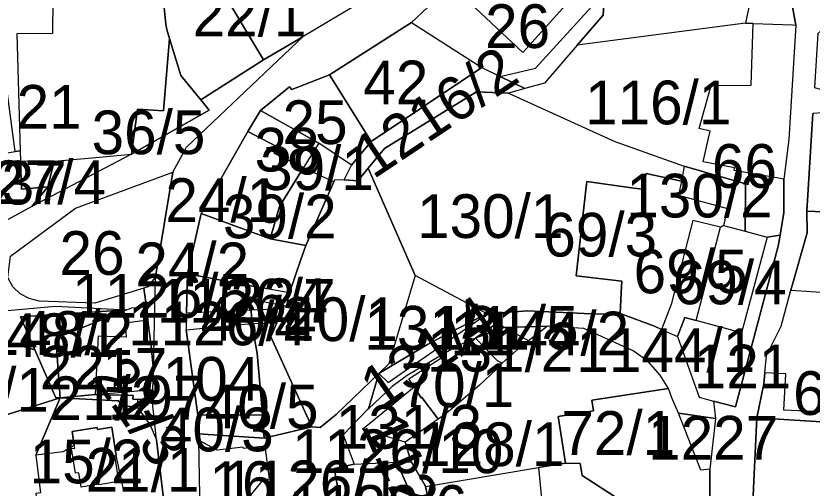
# Model space of a CAD drawing. Extents: x -623250 to -619626, y -1079612 to -1075424.
# Drawn here: x -621601 to -621418.9, y -1077445.8 to -1077337.8 of the extents above; entities that cross this region are included whole.
import ezdxf

# ---------------------------------------------------------------- set-up
doc = ezdxf.new("R2010")
doc.units = 0
doc.layers.add('Parcela nároku', color=7, linetype='Continuous')
doc.layers.add('Parcelní číslo', color=7, linetype='Continuous')

msp = doc.modelspace()

# ---------------------------------------------------------------- linework, layer by layer
at = {"layer": 'Parcela nároku'}
for points in [[(-621600.79, -1077341.91), (-621599.98, -1077368.66), (-621601.14, -1077368.85), (-621608.91, -1077310.81), (-621614.46, -1077275.5), (-621617.74, -1077254.62), (-621618.44, -1077250.2), (-621584.31, -1077246.2), (-621576.81, -1077248.47), (-621571.17, -1077298.59), (-621567.58, -1077330.5), (-621592.44, -1077330.4), (-621592.59, -1077340.5), (-621592.59, -1077341.84)], [(-621538.85, -1077280.06), (-621571.17, -1077298.59), (-621567.58, -1077330.5), (-621566.7, -1077339.72), (-621566.45, -1077340.93), (-621565.82, -1077343), (-621563.28, -1077351.43), (-621558.7, -1077357.03), (-621544.35, -1077347.86), (-621555.55, -1077329.09), (-621547.19, -1077324.12), (-621539.75, -1077319.7), (-621541.19, -1077317.29), (-621534.31, -1077313.2), (-621540.47, -1077302.78), (-621526.88, -1077291.7), (-621533.5, -1077284.61)], [(-621434.34, -1077279.24), (-621430.86, -1077291.13), (-621432.17, -1077292.28), (-621438.74, -1077291.36), (-621448.7, -1077303.36), (-621460.94, -1077315.92), (-621466.21, -1077330.18), (-621466.69, -1077337.64), (-621472.59, -1077344.5), (-621480.06, -1077353.2), (-621484.6, -1077354.45), (-621490.21, -1077351.69), (-621482.13, -1077349.74), (-621469.37, -1077335.72), (-621469.69, -1077327.4), (-621464.19, -1077314.37), (-621453.57, -1077303.62), (-621441.05, -1077289.32), (-621435.63, -1077281.18)], [(-621440.32, -1077334.33), (-621433.33, -1077335.82), (-621434.1, -1077339.5), (-621472.59, -1077344.5), (-621466.69, -1077337.64), (-621466.21, -1077330.18), (-621460.94, -1077315.92), (-621448.7, -1077303.36), (-621438.74, -1077291.36), (-621432.17, -1077292.28), (-621427.72, -1077298.01), (-621426.4, -1077312.7), (-621428.83, -1077304.68), (-621438.65, -1077307.63), (-621436.09, -1077315.53), (-621436.48, -1077317.28)], [(-621426.4, -1077312.7), (-621428.83, -1077304.68), (-621438.65, -1077307.63), (-621436.09, -1077315.53), (-621436.48, -1077317.28), (-621440.32, -1077334.33), (-621433.33, -1077335.82), (-621434.1, -1077339.5), (-621432.38, -1077339.59), (-621423.38, -1077339.89), (-621422.64, -1077339.94), (-621424.02, -1077331.91), (-621426.21, -1077319.12)], [(-621534.31, -1077313.2), (-621541.19, -1077317.29), (-621539.75, -1077319.7), (-621547.19, -1077324.12), (-621555.55, -1077329.09), (-621544.35, -1077347.86), (-621536.28, -1077343.1), (-621535.09, -1077342.4), (-621521.75, -1077334.48), (-621530.34, -1077319.92)], [(-621492.61, -1077328.02), (-621495.56, -1077325.19), (-621510.49, -1077339.36), (-621494.39, -1077349.63), (-621490.21, -1077351.69), (-621482.13, -1077349.74), (-621469.37, -1077335.72), (-621469.69, -1077327.4), (-621482.14, -1077312.1), (-621489.64, -1077319.57), (-621479, -1077329.07), (-621473.85, -1077333.67), (-621485.07, -1077346.16), (-621498.3, -1077333.67)], [(-621473.85, -1077333.67), (-621479, -1077329.07), (-621489.64, -1077319.57), (-621495.56, -1077325.19), (-621492.61, -1077328.02), (-621498.3, -1077333.67), (-621485.07, -1077346.16)], [(-621592.59, -1077340.5), (-621592.59, -1077341.84), (-621600.79, -1077341.91), (-621599.98, -1077368.66), (-621599.89, -1077370.95), (-621592.24, -1077371.02), (-621590.5, -1077370.88), (-621582.71, -1077370.17), (-621574.55, -1077369.43), (-621573.15, -1077359.17), (-621567.25, -1077359.56), (-621565.82, -1077343), (-621566.45, -1077340.93), (-621566.7, -1077339.72), (-621567.58, -1077330.5), (-621592.44, -1077330.4)], [(-621379.17, -1077372.99), (-621383.87, -1077336.3), (-621412.76, -1077337.56), (-621417.57, -1077341.86), (-621418.32, -1077354.2), (-621414.45, -1077355.34), (-621414.57, -1077350.94), (-621414.74, -1077344.54), (-621399.69, -1077344.22), (-621399.53, -1077350.53), (-621399.5, -1077351.73), (-621390.49, -1077351.5), (-621390.14, -1077367.74), (-621399.09, -1077368.05), (-621411.39, -1077368.36), (-621414.09, -1077368.43), (-621414.24, -1077362.93), (-621414.33, -1077359.83), (-621418.69, -1077360.17), (-621420.08, -1077382.44), (-621380.43, -1077384.11)], [(-621510.49, -1077339.36), (-621494.39, -1077349.63), (-621519.69, -1077366.53), (-621529.22, -1077351.28)], [(-621434.13, -1077376.21), (-621434.19, -1077387.03), (-621429.2, -1077388.44), (-621426.22, -1077387.99), (-621425.34, -1077382.75), (-621425.37, -1077375.13), (-621426.96, -1077374.88), (-621436.7, -1077373.18), (-621436.67, -1077372.57), (-621443.81, -1077371.16), (-621442.58, -1077365.76), (-621442.21, -1077364.21), (-621444.71, -1077363.56), (-621442.16, -1077354.24), (-621442.03, -1077353.76), (-621432.85, -1077353.64), (-621432.38, -1077339.59), (-621434.1, -1077339.5), (-621472.59, -1077344.5), (-621480.06, -1077353.2), (-621484.6, -1077354.45), (-621488.31, -1077355.48), (-621464.03, -1077366.57), (-621448.14, -1077372.19)], [(-621436.7, -1077373.18), (-621436.67, -1077372.57), (-621443.81, -1077371.16), (-621442.58, -1077365.76), (-621442.21, -1077364.21), (-621444.71, -1077363.56), (-621442.16, -1077354.24), (-621442.03, -1077353.76), (-621432.85, -1077353.64), (-621432.38, -1077339.59), (-621423.38, -1077339.89), (-621422.64, -1077339.94), (-621424.22, -1077366.08), (-621425.37, -1077375.13), (-621426.96, -1077374.88)], [(-621558.7, -1077357.03), (-621563.28, -1077351.43), (-621565.82, -1077343), (-621567.25, -1077359.56), (-621573.15, -1077359.17), (-621574.55, -1077369.43), (-621556.8, -1077359.35)], [(-621524.2, -1077371.94), (-621519.69, -1077366.53), (-621494.39, -1077349.63), (-621490.21, -1077351.69), (-621484.6, -1077354.45), (-621488.31, -1077355.48), (-621495.61, -1077355.2), (-621516.65, -1077368.16), (-621520.4, -1077372.67), (-621522.76, -1077375.51), (-621525.93, -1077375.32)], [(-621545.03, -1077359.49), (-621538.38, -1077354.07), (-621537.9, -1077354.66), (-621529.22, -1077351.28), (-621519.69, -1077366.53), (-621524.2, -1077371.94), (-621531.73, -1077366.96)], [(-621472.87, -1077397.29), (-621462.39, -1077398.51), (-621462.44, -1077399.6), (-621462.78, -1077405.91), (-621467.82, -1077406.05), (-621483.88, -1077405.25), (-621493.23, -1077405.99), (-621509.64, -1077397.21), (-621520.4, -1077372.67), (-621516.65, -1077368.16), (-621495.61, -1077355.2), (-621488.31, -1077355.48), (-621464.03, -1077366.57), (-621448.14, -1077372.19), (-621448.79, -1077375.65), (-621456.84, -1077373.89), (-621457.65, -1077377.44), (-621459.62, -1077377.18), (-621470.4, -1077375.71), (-621470.64, -1077377.59)], [(-621545.03, -1077359.49), (-621531.73, -1077366.96), (-621535.2, -1077372.52), (-621541.94, -1077369.2), (-621541.22, -1077367.79), (-621547.92, -1077364.23)], [(-621558.62, -1077383), (-621547.92, -1077364.23), (-621541.22, -1077367.79), (-621541.94, -1077369.2), (-621535.2, -1077372.52), (-621540.69, -1077381.38), (-621542.85, -1077388.78), (-621551.12, -1077385.75)], [(-621531.73, -1077366.96), (-621535.2, -1077372.52), (-621528.3, -1077375.8), (-621528.05, -1077375.2), (-621525.93, -1077375.32), (-621524.2, -1077371.94)], [(-621601.14, -1077368.85), (-621599.98, -1077368.66), (-621599.89, -1077370.95), (-621599.68, -1077377.48), (-621593.69, -1077376.92), (-621597.29, -1077381.44), (-621627.71, -1077398.04), (-621629.08, -1077393.14), (-621618.11, -1077380.62), (-621616.18, -1077371.29), (-621610.38, -1077370.32)], [(-621592.24, -1077371.02), (-621590.5, -1077370.88), (-621582.71, -1077370.17), (-621574.55, -1077369.43), (-621597.29, -1077381.44), (-621593.69, -1077376.92)], [(-621599.89, -1077370.95), (-621592.24, -1077371.02), (-621593.69, -1077376.92), (-621599.68, -1077377.48)], [(-621587.33, -1077381.8), (-621565.08, -1077373.54), (-621569.08, -1077397.48), (-621570.82, -1077399.79), (-621571.73, -1077400.07), (-621582.93, -1077403.5), (-621595.64, -1077403.04), (-621597.93, -1077402.44), (-621599.99, -1077401.39), (-621601.64, -1077399.77), (-621602.8, -1077397.67), (-621602.22, -1077392.75)], [(-621535.2, -1077372.52), (-621528.3, -1077375.8), (-621534.63, -1077390.3), (-621542.85, -1077388.78), (-621540.69, -1077381.38)], [(-621528.3, -1077375.8), (-621528.05, -1077375.2), (-621525.93, -1077375.32), (-621522.76, -1077375.51), (-621520.4, -1077372.67), (-621509.64, -1077397.21), (-621515.68, -1077417.42), (-621517.95, -1077419.57), (-621527.71, -1077428.99), (-621531.37, -1077431.97), (-621533.26, -1077431.82), (-621542.67, -1077411.2), (-621541.3, -1077408), (-621539.94, -1077404.78), (-621539.64, -1077404.07), (-621538.98, -1077404.2), (-621538.42, -1077401.19), (-621535.82, -1077393.52), (-621534.63, -1077390.3)], [(-621448.79, -1077375.65), (-621449.45, -1077378.83), (-621438.25, -1077381.86), (-621439.12, -1077385.73), (-621434.19, -1077387.03), (-621434.13, -1077376.21), (-621448.14, -1077372.19)], [(-621470.4, -1077375.71), (-621459.62, -1077377.18), (-621457.65, -1077377.44), (-621456.84, -1077373.89), (-621448.79, -1077375.65), (-621449.45, -1077378.83), (-621438.25, -1077381.86), (-621439.12, -1077385.73), (-621439.86, -1077386.13), (-621446.17, -1077384.61), (-621451.13, -1077403.82), (-621453.32, -1077409.51), (-621454.95, -1077408.78), (-621462.78, -1077405.91), (-621462.44, -1077399.6), (-621462.39, -1077398.51), (-621472.87, -1077397.29), (-621470.64, -1077377.59)], [(-621420.01, -1077387.44), (-621423.72, -1077400.54), (-621405.16, -1077401.74), (-621405.62, -1077410.25), (-621406.08, -1077418.95), (-621406.7, -1077428.87), (-621425.38, -1077428), (-621424.88, -1077419.72), (-621429.71, -1077419.47), (-621429.96, -1077421.94), (-621431.55, -1077429.78), (-621387.12, -1077432.52), (-621384.11, -1077410.75), (-621380.43, -1077384.11), (-621420.08, -1077382.44)], [(-621542.85, -1077388.78), (-621534.63, -1077390.3), (-621535.82, -1077393.52), (-621538.42, -1077401.19), (-621544.35, -1077400.08), (-621561.72, -1077396.82), (-621558.62, -1077383), (-621551.12, -1077385.75)], [(-621446.17, -1077384.61), (-621451.13, -1077403.82), (-621453.32, -1077409.51), (-621449.67, -1077411.15), (-621448.01, -1077406.8), (-621445.38, -1077407.51), (-621439.86, -1077386.13)], [(-621445.38, -1077407.51), (-621439.86, -1077386.13), (-621439.12, -1077385.73), (-621434.19, -1077387.03), (-621429.2, -1077388.44), (-621435, -1077410.33)], [(-621445.38, -1077407.51), (-621448.01, -1077406.8), (-621449.67, -1077411.15), (-621444.7, -1077425.04), (-621441.44, -1077425.9), (-621436.38, -1077427.24), (-621426.64, -1077390.48), (-621426.22, -1077387.99), (-621429.2, -1077388.44), (-621435, -1077410.33)], [(-621544.9, -1077403.08), (-621539.64, -1077404.07), (-621539.94, -1077404.78), (-621547.14, -1077405.1), (-621561.94, -1077405.77), (-621561.72, -1077396.82), (-621544.35, -1077400.08)], [(-621515.68, -1077417.42), (-621517.95, -1077419.57), (-621515.65, -1077418.24), (-621511.33, -1077415.66), (-621506.84, -1077412.99), (-621501.61, -1077410.13), (-621495.26, -1077406.93), (-621493.23, -1077405.99), (-621509.64, -1077397.21)], [(-621570.82, -1077399.79), (-621571.73, -1077400.07), (-621571.13, -1077404.37), (-621571.05, -1077404.91), (-621570.78, -1077407.39), (-621569.98, -1077414.08), (-621569.54, -1077418.79), (-621569.08, -1077397.48)], [(-621538.42, -1077401.19), (-621544.35, -1077400.08), (-621544.9, -1077403.08), (-621539.64, -1077404.07), (-621538.98, -1077404.2)], [(-621425.97, -1077408.77), (-621423.72, -1077400.54), (-621405.16, -1077401.74), (-621405.62, -1077410.25), (-621406.08, -1077418.95), (-621406.7, -1077428.87), (-621425.38, -1077428), (-621424.88, -1077419.72), (-621429.71, -1077419.47), (-621429.3, -1077415.48)], [(-621607.45, -1077411.04), (-621603.75, -1077405.28), (-621591.99, -1077404.24), (-621575.61, -1077405.07), (-621599.94, -1077406.64), (-621596.63, -1077414.23)], [(-621574.48, -1077404.61), (-621571.13, -1077404.37), (-621571.05, -1077404.91), (-621570.78, -1077407.39), (-621575.95, -1077408.09), (-621575.72, -1077411.26), (-621582.16, -1077411.03), (-621582.82, -1077424.39), (-621590.81, -1077425.21), (-621591.83, -1077411.56), (-621575.61, -1077405.07)], [(-621591.83, -1077411.56), (-621590.81, -1077425.21), (-621591.86, -1077425.16), (-621596.63, -1077414.23), (-621599.94, -1077406.64), (-621575.61, -1077405.07)], [(-621547.14, -1077405.1), (-621561.94, -1077405.77), (-621562.03, -1077409.62), (-621547.03, -1077408.14)], [(-621539.94, -1077404.78), (-621547.14, -1077405.1), (-621547.03, -1077408.14), (-621541.3, -1077408)], [(-621517.95, -1077419.57), (-621515.81, -1077421.63), (-621493.23, -1077405.99), (-621483.88, -1077405.25), (-621467.82, -1077406.05), (-621462.78, -1077405.91), (-621454.95, -1077408.78), (-621453.32, -1077409.51), (-621449.67, -1077411.15), (-621444.7, -1077425.04), (-621441.44, -1077425.9), (-621441.01, -1077429.91), (-621449.46, -1077428.7), (-621450.93, -1077425.2), (-621451.75, -1077423), (-621453.66, -1077420.01), (-621456.4, -1077416.9), (-621459.78, -1077414.4), (-621471.08, -1077409.3), (-621479.38, -1077408.78), (-621487, -1077409.02), (-621489.26, -1077409.05), (-621490.98, -1077408.1), (-621495.85, -1077411.52), (-621499.95, -1077413.28), (-621505.31, -1077416.39), (-621511.49, -1077420.06), (-621514.92, -1077422.55), (-621520.35, -1077427.68)], [(-621511.33, -1077415.66), (-621515.65, -1077418.24), (-621517.95, -1077419.57), (-621515.81, -1077421.63), (-621493.23, -1077405.99), (-621495.26, -1077406.93), (-621501.61, -1077410.13), (-621506.84, -1077412.99)], [(-621582.16, -1077411.03), (-621582.82, -1077424.39), (-621569.69, -1077423.27), (-621569.54, -1077418.79), (-621569.98, -1077414.08), (-621570.78, -1077407.39), (-621575.95, -1077408.09), (-621575.72, -1077411.26)], [(-621547.03, -1077408.14), (-621545.76, -1077415), (-621545.1, -1077422.71), (-621544.56, -1077429.09), (-621559.34, -1077429.16), (-621562.03, -1077409.62)], [(-621542.67, -1077411.2), (-621533.26, -1077431.82), (-621544.21, -1077434.42), (-621544.56, -1077429.09), (-621545.1, -1077422.71), (-621545.76, -1077415), (-621547.03, -1077408.14), (-621541.3, -1077408)], [(-621495.85, -1077411.52), (-621490.98, -1077408.1), (-621489.26, -1077409.05)], [(-621502.93, -1077429.08), (-621504.38, -1077430.07), (-621511.92, -1077435.34), (-621510.57, -1077439.83), (-621507.3, -1077445.44), (-621481.49, -1077441.1), (-621475.26, -1077440.11), (-621476.98, -1077429.42), (-621468.9, -1077428.12), (-621469.29, -1077425.7), (-621466.76, -1077425.29), (-621451.75, -1077423), (-621453.66, -1077420.01), (-621456.4, -1077416.9), (-621459.78, -1077414.4), (-621471.08, -1077409.3), (-621479.38, -1077408.78), (-621483.72, -1077412.1), (-621484.93, -1077413), (-621489.79, -1077417.27), (-621491.17, -1077418.72), (-621494.92, -1077422.28), (-621500.25, -1077426.86)], [(-621489.26, -1077409.05), (-621495.85, -1077411.52), (-621490.9, -1077416.64), (-621489.79, -1077417.27), (-621484.93, -1077413), (-621483.72, -1077412.1)], [(-621487, -1077409.02), (-621479.38, -1077408.78), (-621483.72, -1077412.1), (-621489.26, -1077409.05)], [(-621623.02, -1077425.7), (-621607.45, -1077411.04), (-621596.63, -1077414.23), (-621591.86, -1077425.16), (-621590.81, -1077425.21), (-621608.27, -1077430.64), (-621625.29, -1077427.92)], [(-621514.92, -1077422.55), (-621520.35, -1077427.68), (-621520.64, -1077427.95), (-621526.14, -1077433.6), (-621523.62, -1077440.31), (-621513.83, -1077439.85), (-621510.57, -1077439.83), (-621511.92, -1077435.34), (-621521.73, -1077432.32), (-621509.91, -1077422.66), (-621511.09, -1077420.83), (-621503.6, -1077415.98), (-621502.71, -1077417.23), (-621501.46, -1077416.29), (-621499.1, -1077414.64), (-621495.85, -1077411.52), (-621499.95, -1077413.28), (-621505.31, -1077416.39), (-621511.49, -1077420.06)], [(-621495.85, -1077411.52), (-621490.9, -1077416.64), (-621489.79, -1077417.27), (-621491.17, -1077418.72), (-621494.92, -1077422.28), (-621500.25, -1077426.86), (-621502.93, -1077429.08), (-621504.38, -1077430.07), (-621504.79, -1077429.52), (-621508.12, -1077425.06), (-621508.28, -1077425.17), (-621509.91, -1077422.66), (-621511.09, -1077420.83), (-621503.6, -1077415.98), (-621502.71, -1077417.23), (-621501.46, -1077416.29), (-621499.1, -1077414.64)], [(-621508.12, -1077425.06), (-621504.79, -1077429.52), (-621504.38, -1077430.07), (-621511.92, -1077435.34), (-621521.73, -1077432.32), (-621509.91, -1077422.66), (-621508.28, -1077425.17)], [(-621574.2, -1077425.49), (-621573.14, -1077425.56), (-621573.22, -1077427.34), (-621576.22, -1077427), (-621577.59, -1077425.88), (-621590.81, -1077425.21), (-621582.82, -1077424.39), (-621574.17, -1077424.62)], [(-621582.82, -1077424.39), (-621569.69, -1077423.27), (-621569.77, -1077425.55), (-621573.14, -1077425.56), (-621574.2, -1077425.49), (-621574.17, -1077424.62)], [(-621451.75, -1077423), (-621466.76, -1077425.29), (-621469.29, -1077425.7), (-621468.9, -1077428.12), (-621476.98, -1077429.42), (-621475.26, -1077440.11), (-621471.93, -1077440.18), (-621471.5, -1077442.95), (-621452.51, -1077455.2), (-621442.23, -1077454.31), (-621442.3, -1077441.52), (-621444.35, -1077441.74), (-621449.46, -1077428.7), (-621450.93, -1077425.2)], [(-621651.71, -1077428.55), (-621625.29, -1077427.92), (-621608.27, -1077430.64), (-621590.81, -1077425.21), (-621596.41, -1077438.29), (-621595.37, -1077446.92), (-621596.41, -1077447.05), (-621596.32, -1077447.8), (-621599.98, -1077451.17), (-621607.92, -1077449.11), (-621609.14, -1077444.92), (-621615.21, -1077439.45), (-621626.72, -1077438.85), (-621649.84, -1077437.65)], [(-621568.85, -1077434.75), (-621569.77, -1077425.55), (-621573.14, -1077425.56), (-621573.22, -1077427.34), (-621570.36, -1077431.24)], [(-621544.56, -1077429.09), (-621544.21, -1077434.42), (-621559.26, -1077433.41), (-621559.34, -1077429.16)], [(-621449.46, -1077428.7), (-621441.01, -1077429.91), (-621442.3, -1077441.52), (-621444.35, -1077441.74)], [(-621431.19, -1077464.42), (-621432.42, -1077476.42), (-621394.2, -1077479.27), (-621389.22, -1077446.41), (-621387.12, -1077432.52), (-621431.55, -1077429.78), (-621432.54, -1077450.72)], [(-621588.25, -1077436.78), (-621587.51, -1077436.66), (-621587.61, -1077436.07), (-621588.12, -1077432.87), (-621582.36, -1077431.97), (-621582.29, -1077432.4), (-621579.02, -1077431.89), (-621578.01, -1077438.34), (-621578.41, -1077438.46), (-621577.65, -1077443.25), (-621577.51, -1077444.3), (-621582.01, -1077445.04), (-621582.03, -1077444.94), (-621586.06, -1077445.6), (-621586.61, -1077442.29), (-621587.31, -1077442.4)], [(-621547.56, -1077449.24), (-621547.71, -1077447.97), (-621544.37, -1077443.86), (-621543.01, -1077443.69), (-621543.93, -1077436.2), (-621548.94, -1077436.76), (-621548.97, -1077436.47), (-621554.97, -1077437.15), (-621559.23, -1077434.88), (-621558.89, -1077451.75), (-621556.54, -1077458.83), (-621548.86, -1077449.39)], [(-621523.62, -1077440.31), (-621513.83, -1077439.85), (-621507.7, -1077453.97), (-621510.81, -1077454.77), (-621512.86, -1077470.31), (-621518.98, -1077469.95), (-621519.69, -1077452.67), (-621524.33, -1077452.43), (-621526.15, -1077452.32), (-621528.22, -1077441.35)], [(-621507.3, -1077445.44), (-621505.58, -1077453.42), (-621507.7, -1077453.97), (-621513.83, -1077439.85), (-621510.57, -1077439.83)], [(-621507.3, -1077445.44), (-621481.49, -1077441.1), (-621479.17, -1077464.9), (-621503.43, -1077463.41), (-621505.07, -1077455.79), (-621505.58, -1077453.42)], [(-621442.07, -1077471), (-621442.35, -1077467.18), (-621441.68, -1077467.22), (-621442.23, -1077454.31), (-621452.51, -1077455.2), (-621471.5, -1077442.95), (-621471.93, -1077440.18), (-621475.26, -1077440.11), (-621481.49, -1077441.1), (-621479.17, -1077464.9), (-621467.73, -1077465.6), (-621454.56, -1077468.37)]]:
    msp.add_lwpolyline(points, close=True, dxfattribs=at)
for points in [[(-621495.56, -1077325.19), (-621510.49, -1077339.36), (-621529.22, -1077351.28), (-621537.9, -1077354.66), (-621538.38, -1077354.07), (-621545.03, -1077359.49), (-621547.92, -1077364.23), (-621558.62, -1077383), (-621561.72, -1077396.82), (-621561.94, -1077405.77), (-621562.03, -1077409.62), (-621559.34, -1077429.16), (-621559.26, -1077433.41), (-621559.23, -1077434.88), (-621558.89, -1077451.75)], [(-621424.02, -1077331.91), (-621422.64, -1077339.94), (-621424.22, -1077366.08), (-621425.37, -1077375.13), (-621425.34, -1077382.75), (-621426.22, -1077387.99), (-621426.64, -1077390.48), (-621436.38, -1077427.24), (-621441.44, -1077425.9), (-621441.01, -1077429.91), (-621442.3, -1077441.52), (-621442.23, -1077454.31)], [(-621566.72, -1077452.69), (-621568.85, -1077434.75), (-621569.77, -1077425.55), (-621569.69, -1077423.27), (-621569.54, -1077418.79), (-621569.08, -1077397.48), (-621565.08, -1077373.54), (-621561.99, -1077367.81), (-621535.09, -1077342.4), (-621521.75, -1077334.48)], [(-621602.22, -1077392.75), (-621587.33, -1077381.8), (-621565.08, -1077373.54), (-621561.99, -1077367.81), (-621535.09, -1077342.4), (-621536.28, -1077343.1), (-621544.35, -1077347.86), (-621558.7, -1077357.03), (-621556.8, -1077359.35), (-621574.55, -1077369.43), (-621597.29, -1077381.44), (-621627.71, -1077398.04)], [(-621432.54, -1077450.72), (-621431.55, -1077429.78), (-621429.96, -1077421.94), (-621429.71, -1077419.47), (-621429.3, -1077415.48), (-621425.97, -1077408.77), (-621423.72, -1077400.54), (-621420.01, -1077387.44), (-621420.08, -1077382.44), (-621418.69, -1077360.17)], [(-621603.75, -1077405.28), (-621591.99, -1077404.24), (-621575.61, -1077405.07), (-621574.48, -1077404.61), (-621571.13, -1077404.37), (-621571.73, -1077400.07), (-621582.93, -1077403.5), (-621595.64, -1077403.04), (-621597.93, -1077402.44), (-621599.99, -1077401.39), (-621601.64, -1077399.77)], [(-621547.71, -1077447.97), (-621544.37, -1077443.86), (-621543.01, -1077443.69), (-621543.93, -1077436.2), (-621548.94, -1077436.76), (-621548.97, -1077436.47), (-621554.97, -1077437.15), (-621559.23, -1077434.88), (-621559.26, -1077433.41), (-621544.21, -1077434.42), (-621533.26, -1077431.82), (-621531.37, -1077431.97), (-621527.71, -1077428.99), (-621517.95, -1077419.57), (-621520.35, -1077427.68), (-621520.64, -1077427.95), (-621526.14, -1077433.6), (-621523.62, -1077440.31), (-621528.22, -1077441.35), (-621526.15, -1077452.32)], [(-621576.31, -1077446.48), (-621578.01, -1077438.34), (-621579.02, -1077431.89), (-621582.29, -1077432.4), (-621582.36, -1077431.97), (-621588.12, -1077432.87), (-621587.61, -1077436.07), (-621590.26, -1077437.55), (-621596.41, -1077438.29), (-621590.81, -1077425.21), (-621577.59, -1077425.88), (-621576.22, -1077427), (-621573.22, -1077427.34), (-621570.36, -1077431.24), (-621568.85, -1077434.75), (-621566.72, -1077452.69)], [(-621576.31, -1077446.48), (-621578.01, -1077438.34), (-621578.41, -1077438.46), (-621577.65, -1077443.25), (-621577.51, -1077444.3), (-621582.01, -1077445.04), (-621582.03, -1077444.94), (-621586.06, -1077445.6), (-621586.61, -1077442.29), (-621587.31, -1077442.4), (-621588.25, -1077436.78), (-621587.51, -1077436.66), (-621587.61, -1077436.07), (-621590.26, -1077437.55), (-621596.41, -1077438.29), (-621595.37, -1077446.92)]]:
    msp.add_lwpolyline(points, dxfattribs=at)

# ---------------------------------------------------------------- texts
at = {"layer": 'Parcelní číslo'}
for s, p in [('22/1', (-621560.55, -1077342.51)), ('26', (-621493.67, -1077345.16)), ('42', (-621521.53, -1077358.04)), ('21', (-621600.8, -1077363.62)), ('116/1', (-621470.81, -1077362.62)), ('25', (-621539.99, -1077367.13)), ('36/5', (-621583.66, -1077369.45)), ('38', (-621546.4, -1077373.41)), ('39/1', (-621545.13, -1077377.65)), ('66', (-621441.81, -1077377.14)), ('27/4', (-621606.37, -1077380.87)), ('37', (-621604.22, -1077380.95)), ('130/2', (-621461.37, -1077383.92)), ('24/1', (-621566.78, -1077384.95)), ('39/2', (-621553.63, -1077388.68)), ('130/1', (-621509.23, -1077388.61)), ('69/3', (-621480.36, -1077392.85)), ('26', (-621590.99, -1077397.04)), ('24/2', (-621573.66, -1077399.65)), ('69/5', (-621459.7, -1077401.26)), ('69/4', (-621450.73, -1077403.77)), ('1126/5', (-621588.11, -1077406.87)), ('1126/7', (-621568.76, -1077407.97)), ('224', (-621551.89, -1077407.86)), ('1126/4', (-621575.3, -1077413.15)), ('40/2', (-621558.71, -1077412.13)), ('40/1', (-621539.62, -1077412.2)), ('131/1', (-621521.29, -1077414.15)), ('131/5', (-621505.75, -1077414.14)), ('1148/1', (-621618.24, -1077415.86)), ('1148/2', (-621615.07, -1077415.34)), ('1144/2', (-621501.62, -1077415.46)), ('131/2', (-621506.95, -1077419.17)), ('1144/1', (-621472.8, -1077419.28)), ('22', (-621595.49, -1077423.22)), ('121', (-621445.95, -1077423.01)), ('17', (-621581.22, -1077423.81)), ('104', (-621567.42, -1077425.82)), ('70/1', (-621513.01, -1077427.3)), ('24/1', (-621619.44, -1077428.36)), ('68', (-621423.23, -1077429.08)), ('21/2', (-621593.28, -1077430.27)), ('197', (-621579.93, -1077430.13)), ('40/5', (-621557.78, -1077432.17)), ('131/3', (-621527.81, -1077436.81)), ('40/3', (-621568.03, -1077437.41)), ('72/1', (-621476.23, -1077438.22)), ('1227', (-621456.38, -1077439.31)), ('1126/10', (-621537.85, -1077442.4)), ('128/1', (-621508.99, -1077440.8)), ('15/2', (-621597.82, -1077444.73)), ('21/1', (-621585.02, -1077446.64)), ('1126/1', (-621553.78, -1077449.52)), ('16', (-621556.7, -1077449.7)), ('1126/6', (-621538.61, -1077455.14))]:
    msp.add_text(s, height=10, dxfattribs=at).set_placement(p)
for s, rotation, p in [('1216/2', 33.7423, (-621519.27, -1077375.3)), ('131/4', 34.7083, (-621517.57, -1077428.42)), ('21/3', 304.3006, (-621583.77, -1077420.25)), ('1126/11', 293.4686, (-621522.04, -1077431.51))]:
    msp.add_text(s, height=10, rotation=rotation, dxfattribs=at).set_placement(p)

doc.saveas('drawing.dxf')
